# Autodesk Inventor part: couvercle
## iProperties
Created: 2001-10
Part Number: couvercle
Material: Par défaut
Document SubType Name: Modélisation
Designer: User
Control State: 0
Master: False
Checked Out: False
Shininess: 20.0
Length Units: 11269
Angle Units: 11279
Time Units: 11290
Mass Units: 11283
Length Display Precision: 3
Angle Display Precision: 2
Density: 0.0
Volumn: 0.0
Area: 0.0
PropertySet Name: Model Information
Author: User
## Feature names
1. Extrusion1
2. Perçage1 [Hole]
3. Congé1 [Fillet]
4. Coque1
5. Chanfrein1 [Chamfer]
6. Extrusion2
7. Perçage2 [Hole]
8. Extrusion3
9. Symétrie3 [Mirror]
10. Symétrie4 [Mirror]
11. Extrusion4
12. Réseau circulaire1 [Circular Pattern]
13. Extrusion5
14. Congé2 [Fillet]
15. Extrusion6
16. Extrusion7
17. Extrusion8
18. Extrusion9
19. Extrusion10
20. Symétrie5 [Mirror]
21. Extrusion11
22. Symétrie6 [Mirror]
23. Extrusion12
